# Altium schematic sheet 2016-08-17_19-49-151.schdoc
size 327 x 144 mm; SheetNumber: 1; SheetTotal: 1
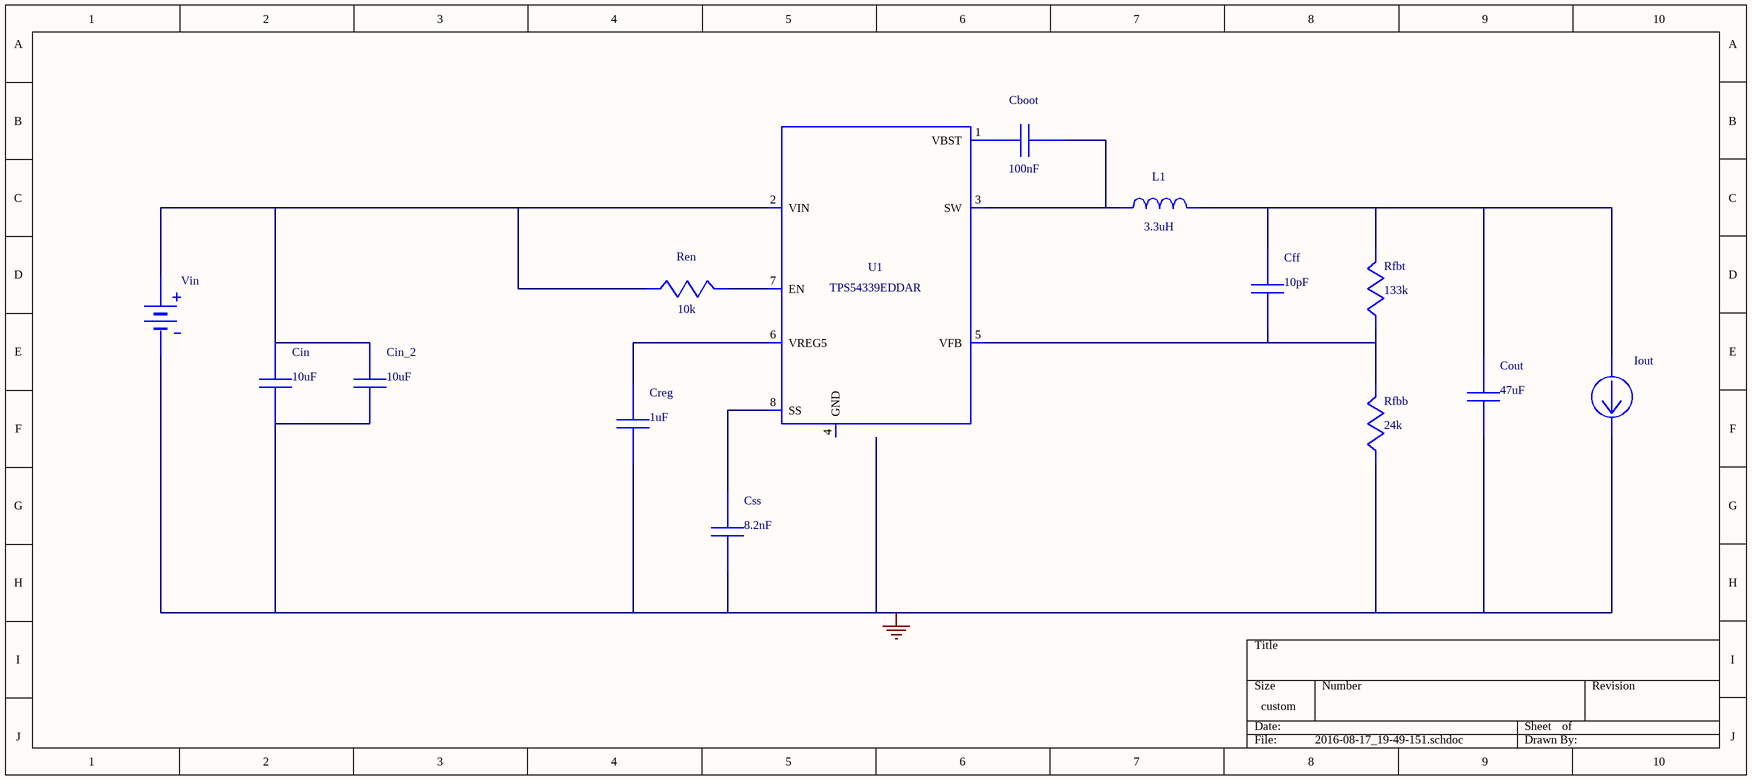
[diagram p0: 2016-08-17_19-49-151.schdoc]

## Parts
Cboot  value 100nF  (hidden comment: GRM155R61A104KA01D)
Cff  value 10pF  (hidden comment: C0805C100M4GACTU)
Cin  value 10uF  (hidden comment: GRM32ER7YA106KA12L)
Cin_2  value 10uF  (hidden comment: GRM32ER7YA106KA12L)
Cout  value 47uF  (hidden comment: C3216JB1A476M)
Creg  value 1uF  (hidden comment: GRM188R61A105KA61D)
Css  value 8.2nF  (hidden comment: GRM033R61A822KA01D)
Iout  WB_CURRENT_LOAD  (value not drawn)
L1  value 3.3uH  (hidden comment: CLF7045T-3R3N)
Ren  value 10k  (hidden comment: CRCW040210K0FKED)
Rfbb  value 24k  (hidden comment: RC0603FR-0724KL)
Rfbt  value 133k  (hidden comment: CRCW0402133KFKED)
U1  TPS54229DDAR  (value not drawn)
Vin  WB_BATTERY  (value not drawn)

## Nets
0: Cin.2 Cin_2.2 Cout.2 Creg.2 Css.2 Iout.2(-) Rfbb.2 Vin.2(-)
NetCboot_1: Cboot.1 U1.1(VBST)
NetCboot_2: Cboot.2 L1.2 U1.3(SW)
NetCff_1: Cff.1 Cout.1 Iout.1(+) L1.1 Rfbt.1
NetCff_2: Cff.2 Rfbb.1 Rfbt.2 U1.5(VFB)
NetCin_1: Cin.1 Cin_2.1 Ren.2 U1.2(VIN) Vin.1(+)
NetCreg_1: Creg.1 U1.6(VREG5)
NetCss_1: Css.1 U1.8(SS)
NetRen_1: Ren.1 U1.7(EN)
NetU1_4: U1.4(GND) U1.9(ETPAD)

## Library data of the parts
Cboot = GRM155R61A104KA01D: GRM155R61A104KA0; Manufacturer Name: MuRata
Cff = C0805C100M4GACTU: Manufacturer Name: Kemet
Cin Cin_2 = GRM32ER7YA106KA12L: GRM32ER7YA106KA1; Manufacturer Name: MuRata
Cout = C3216JB1A476M: Manufacturer Name: TDK
Creg = GRM188R61A105KA61D: GRM188R61A105KA6; Manufacturer Name: MuRata
Css = GRM033R61A822KA01D: GRM033R61A822KA0; Manufacturer Name: MuRata
L1 = CLF7045T-3R3N: Unknown; Manufacturer Name: TDK
Ren = CRCW040210K0FKED: Manufacturer Name: Vishay-Dale
Rfbb = RC0603FR-0724KL: Manufacturer Name: Yageo America
Rfbt = CRCW0402133KFKED: Manufacturer Name: Vishay-Dale
U1 = TPS54229DDAR: TPS54339EDDAR; Manufacturer Name: Texas Instruments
